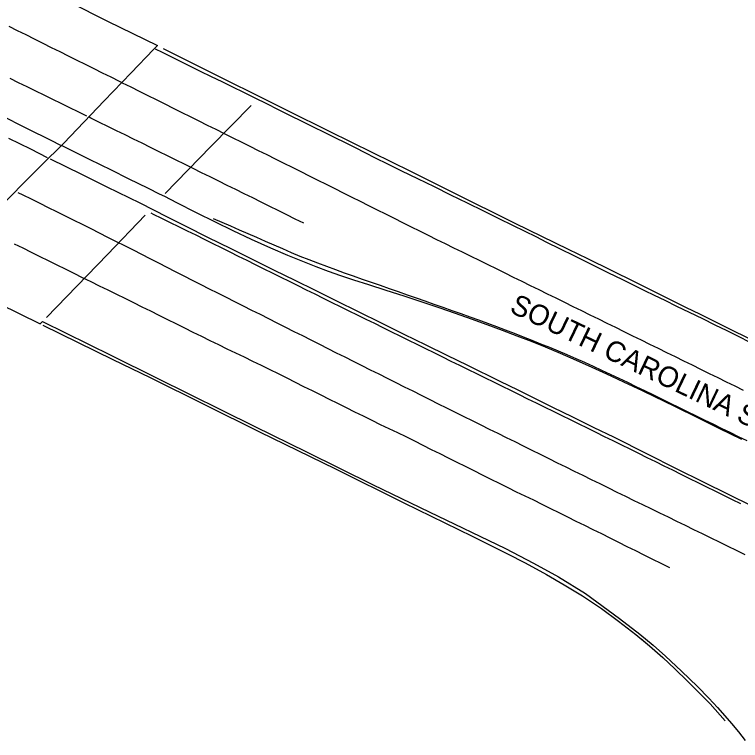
# Model space of a CAD drawing. Extents: x 1961683 to 1977751, y 798292 to 805767.
# Drawn here: x 1963330.2 to 1963521.4, y 799610 to 799801.1 of the extents above; entities that cross this region are included whole.
import ezdxf

# ---------------------------------------------------------------- set-up
doc = ezdxf.new("R2010")
doc.units = 0
for name, color, linetype in [('RD_EX_Bridge', 7, 'Continuous'), ('RD_EX_Conc', 7, 'Continuous'), ('RD_EX_Road', 7, 'Continuous'), ('RD_EX_Road_Paint', 7, 'Continuous'), ('RD_TX_RoadID', 7, 'Continuous')]:
    doc.layers.add(name, color=color, linetype=linetype)

msp = doc.modelspace()

# ---------------------------------------------------------------- linework, layer by layer
at = {"layer": 'RD_EX_Bridge'}
msp.add_lwpolyline([(1963325.6, 799813.75), (1963336.46, 799808.32), (1963344.73, 799804.28), (1963354.67, 799799.34), (1963367.78, 799792.9), (1963366.76, 799791.82), (1963360.89, 799785.69), (1963353.75, 799778.38), (1963343.15, 799767.2), (1963337.18, 799761.34), (1963332.27, 799756.44), (1963323.69, 799747.66)], dxfattribs=at)
at = {"layer": 'RD_EX_Conc'}
for points in [[(1963369.84, 799753.92), (1963381.85, 799766.33), (1963392.52, 799777.14)], [(1963326.11, 799774.71), (1963333.52, 799771.06), (1963339.69, 799768.01), (1963342.3, 799766.71)], [(1963338.88, 799763.39), (1963334.46, 799765.62), (1963328.66, 799768.46)], [(1963521.74, 799689.21), (1963515.78, 799692.13), (1963509.96, 799694.97), (1963504.58, 799697.61), (1963500.99, 799699.37), (1963498.94, 799700.37), (1963495.54, 799702), (1963490.63, 799704.34), (1963486.13, 799706.44), (1963482.26, 799708.2), (1963478.21, 799710), (1963473.95, 799711.86), (1963469.98, 799713.53), (1963466.33, 799715), (1963462.58, 799716.45), (1963458.67, 799717.91), (1963454.63, 799719.39), (1963450.48, 799720.89), (1963446.29, 799722.38), (1963442.04, 799723.85), (1963437.53, 799725.36), (1963432.76, 799726.9), (1963428.05, 799728.42), (1963423.51, 799729.9), (1963419.52, 799731.19), (1963416.09, 799732.32), (1963412.84, 799733.47), (1963409.64, 799734.68), (1963406.12, 799736.05), (1963402.18, 799737.61), (1963397.63, 799739.57), (1963392.56, 799741.88), (1963387.71, 799744.17), (1963383.1, 799746.41), (1963378.1, 799748.9), (1963372.95, 799751.52), (1963369.77, 799753.13), (1963368.36, 799753.83), (1963365.49, 799755.24), (1963360.17, 799757.85), (1963355.71, 799760.06), (1963349.89, 799762.95), (1963342.72, 799766.51)], [(1963339.51, 799763.06), (1963347.79, 799759.03), (1963354.49, 799755.75), (1963363.15, 799751.47), (1963370.36, 799747.84), (1963375.26, 799745.38), (1963381.03, 799742.5), (1963387.1, 799739.46), (1963392.95, 799736.56), (1963398.57, 799733.77), (1963403.96, 799731.12), (1963409.33, 799728.48), (1963414.92, 799725.73), (1963420.7, 799722.88), (1963426.69, 799719.93), (1963432.68, 799716.98), (1963438.47, 799714.13), (1963444.05, 799711.4), (1963449.42, 799708.77), (1963458.01, 799704.57), (1963462.69, 799702.27), (1963467.66, 799699.82), (1963471.83, 799697.77), (1963477.12, 799695.18), (1963482.74, 799692.42), (1963487.89, 799689.88), (1963496.77, 799685.45), (1963504.42, 799681.62), (1963511.5, 799678.09), (1963518.1, 799674.84), (1963524.32, 799671.8)], [(1963338.6, 799721.35), (1963354.63, 799737.94), (1963364.59, 799748.27)]]:
    msp.add_lwpolyline(points, dxfattribs=at)
at = {"layer": 'RD_EX_Road'}
for points in [[(1963523.93, 799714.75), (1963520.8, 799716.31), (1963517.83, 799717.79), (1963514.69, 799719.33), (1963511.4, 799720.94), (1963507.95, 799722.62), (1963504.57, 799724.26), (1963501.48, 799725.76), (1963498.69, 799727.12), (1963496.19, 799728.34), (1963493.55, 799729.63), (1963490.33, 799731.22), (1963486.52, 799733.1), (1963482.13, 799735.27), (1963477.7, 799737.47), (1963473.79, 799739.41), (1963470.39, 799741.09), (1963467.51, 799742.52), (1963464.68, 799743.92), (1963461.44, 799745.52), (1963457.79, 799747.32), (1963453.72, 799749.32), (1963449.43, 799751.43), (1963445.1, 799753.55), (1963440.75, 799755.68), (1963436.36, 799757.82), (1963432.19, 799759.86), (1963428.49, 799761.68), (1963425.26, 799763.28), (1963422.5, 799764.67), (1963419.93, 799765.96), (1963417.29, 799767.28), (1963414.58, 799768.63), (1963411.78, 799770.01), (1963408.9, 799771.42), (1963405.93, 799772.89), (1963402.87, 799774.4), (1963399.72, 799775.96), (1963396.58, 799777.53), (1963393.52, 799779.04), (1963390.55, 799780.51), (1963387.67, 799781.92), (1963384.84, 799783.32), (1963382.01, 799784.7), (1963379.18, 799786.09), (1963376.35, 799787.47), (1963373.66, 799788.79), (1963371.24, 799789.98), (1963369.11, 799791.05), (1963367.25, 799791.98)], [(1963525.71, 799714.75), (1963519.58, 799717.76), (1963514.65, 799720.19), (1963510.79, 799722.09), (1963506.96, 799724), (1963502.38, 799726.27), (1963493.6, 799730.61), (1963487.41, 799733.66), (1963481.17, 799736.73), (1963476.03, 799739.25), (1963469.04, 799742.66), (1963462.05, 799746.08), (1963456.92, 799748.62), (1963450.7, 799751.71), (1963443.28, 799755.39), (1963434.54, 799759.72), (1963424.49, 799764.69), (1963413.13, 799770.31), (1963402.17, 799775.73), (1963393.33, 799780.11), (1963386.6, 799783.45), (1963378.52, 799787.48), (1963372.23, 799790.64), (1963369.4, 799792.07)], [(1963309.51, 799733.08), (1963336.93, 799719.62), (1963337.57, 799720.28), (1963355.71, 799711.33), (1963367.55, 799705.42), (1963393.49, 799692.68), (1963407.1, 799685.97), (1963424.6, 799677.31), (1963439.33, 799670.19), (1963459.48, 799660.5), (1963466.8, 799656.67), (1963473.42, 799653.05), (1963480.5, 799648.67), (1963489.52, 799642.15), (1963494.82, 799638.02), (1963498.4, 799635.09), (1963501.62, 799632.21), (1963505.86, 799628.23), (1963510.03, 799624.19), (1963513.02, 799621.12), (1963515.27, 799618.69), (1963517.2, 799616.52), (1963518.99, 799614.44), (1963520.79, 799612.25), (1963522.58, 799610.01)], [(1963337.59, 799719.33), (1963356.09, 799710.24), (1963365.88, 799705.5), (1963394.69, 799691.26), (1963414.67, 799681.49), (1963432.71, 799672.57), (1963450.67, 799663.8), (1963460, 799659.15), (1963464.63, 799656.8), (1963470.31, 799653.69), (1963474.93, 799651.01), (1963479.72, 799648.11), (1963484.75, 799644.7), (1963489.27, 799641.37), (1963493.79, 799637.92), (1963497.42, 799634.92), (1963500.88, 799631.85), (1963504.06, 799628.87), (1963507.4, 799625.65), (1963509.83, 799623.2), (1963513.35, 799619.63), (1963517.33, 799615.21)], [(1963495.12, 799636.82), (1963497.42, 799634.92), (1963500.88, 799631.85), (1963504.06, 799628.87), (1963507.4, 799625.65), (1963509.83, 799623.2), (1963513.35, 799619.63), (1963517.33, 799615.21)]]:
    msp.add_lwpolyline(points, dxfattribs=at)
at = {"layer": 'RD_EX_Road_Paint'}
for points in [[(1963328.63, 799798), (1963330.87, 799796.88), (1963333.11, 799795.77), (1963335.34, 799794.65), (1963337.58, 799793.54), (1963339.82, 799792.43), (1963342.06, 799791.31), (1963344.3, 799790.2), (1963346.53, 799789.08), (1963348.77, 799787.97), (1963351.01, 799786.86), (1963353.25, 799785.74), (1963355.49, 799784.63), (1963357.72, 799783.52), (1963358.28, 799783.24)], [(1963349.2, 799774.33), (1963346.96, 799775.43), (1963344.71, 799776.53), (1963342.47, 799777.63), (1963340.23, 799778.73), (1963337.98, 799779.83), (1963335.74, 799780.93), (1963333.49, 799782.03), (1963331.25, 799783.13), (1963329, 799784.24)], [(1963358.54, 799783.11), (1963360.77, 799782), (1963363.01, 799780.88), (1963365.25, 799779.77), (1963367.49, 799778.66), (1963369.73, 799777.54), (1963371.97, 799776.43), (1963374.2, 799775.32), (1963376.44, 799774.21), (1963378.68, 799773.09), (1963380.92, 799771.98), (1963383.16, 799770.87), (1963385.4, 799769.76), (1963387.63, 799768.64), (1963389.87, 799767.53), (1963392.11, 799766.42), (1963394.35, 799765.31), (1963396.59, 799764.19), (1963398.83, 799763.08), (1963401.07, 799761.97), (1963403.3, 799760.85), (1963405.54, 799759.74), (1963407.78, 799758.62), (1963410.01, 799757.51), (1963412.25, 799756.39), (1963414.48, 799755.27), (1963416.72, 799754.16), (1963418.96, 799753.04), (1963421.19, 799751.92), (1963423.43, 799750.81), (1963425.67, 799749.69), (1963427.9, 799748.58), (1963430.14, 799747.46), (1963432.37, 799746.34), (1963434.61, 799745.23), (1963436.85, 799744.11), (1963439.08, 799743), (1963441.33, 799741.89), (1963443.57, 799740.79), (1963445.81, 799739.69), (1963448.06, 799738.59), (1963450.3, 799737.48), (1963452.54, 799736.38), (1963454.78, 799735.28), (1963457.03, 799734.18), (1963459.27, 799733.07), (1963461.51, 799731.97), (1963463.76, 799730.87), (1963466, 799729.76), (1963468.24, 799728.66), (1963470.48, 799727.56), (1963472.73, 799726.46), (1963474.97, 799725.35), (1963477.21, 799724.25), (1963479.46, 799723.15), (1963481.7, 799722.05), (1963483.94, 799720.95), (1963486.19, 799719.85), (1963488.43, 799718.75), (1963490.67, 799717.65), (1963492.92, 799716.54), (1963495.16, 799715.44), (1963497.4, 799714.34), (1963499.65, 799713.24), (1963501.89, 799712.14), (1963504.13, 799711.04), (1963506.38, 799709.94), (1963508.62, 799708.84), (1963510.86, 799707.74), (1963513.11, 799706.63), (1963515.35, 799705.53), (1963517.6, 799704.43), (1963519.84, 799703.33), (1963522.08, 799702.23)], [(1963406.33, 799746.14), (1963404.09, 799747.25), (1963401.85, 799748.36), (1963399.61, 799749.47), (1963397.37, 799750.57), (1963395.13, 799751.68), (1963392.89, 799752.79), (1963390.65, 799753.9), (1963388.41, 799755.01), (1963386.17, 799756.11), (1963383.93, 799757.22), (1963381.69, 799758.33), (1963379.45, 799759.44), (1963377.21, 799760.54), (1963374.97, 799761.65), (1963372.73, 799762.76), (1963370.49, 799763.87), (1963368.25, 799764.97), (1963366, 799766.08), (1963363.76, 799767.19), (1963361.52, 799768.29), (1963359.27, 799769.39), (1963357.03, 799770.49), (1963354.78, 799771.59), (1963352.54, 799772.69), (1963350.3, 799773.79), (1963349.83, 799774.02)], [(1963522.58, 799658.88), (1963520.34, 799659.98), (1963518.09, 799661.07), (1963515.85, 799662.17), (1963513.6, 799663.26), (1963511.35, 799664.36), (1963509.11, 799665.46), (1963506.86, 799666.55), (1963504.61, 799667.65), (1963502.37, 799668.74), (1963500.12, 799669.84), (1963497.87, 799670.93), (1963495.63, 799672.03), (1963493.38, 799673.12), (1963491.13, 799674.22), (1963488.89, 799675.31), (1963486.64, 799676.41), (1963484.39, 799677.51), (1963482.15, 799678.61), (1963479.91, 799679.72), (1963477.67, 799680.82), (1963475.43, 799681.93), (1963473.19, 799683.03), (1963470.95, 799684.14), (1963468.7, 799685.25), (1963466.46, 799686.35), (1963464.22, 799687.46), (1963461.98, 799688.57), (1963459.74, 799689.67), (1963457.5, 799690.78), (1963455.26, 799691.89), (1963453.02, 799692.99), (1963450.78, 799694.1), (1963448.54, 799695.21), (1963446.3, 799696.32), (1963444.06, 799697.44), (1963441.83, 799698.56), (1963439.59, 799699.68), (1963437.36, 799700.79), (1963435.12, 799701.91), (1963432.89, 799703.03), (1963430.65, 799704.15), (1963428.42, 799705.26), (1963426.18, 799706.38), (1963423.94, 799707.5), (1963421.71, 799708.62), (1963419.47, 799709.74), (1963417.24, 799710.85), (1963415, 799711.97), (1963412.77, 799713.09), (1963410.53, 799714.21), (1963408.3, 799715.34), (1963406.07, 799716.46), (1963403.84, 799717.58), (1963401.6, 799718.71), (1963399.37, 799719.83), (1963397.14, 799720.96), (1963394.91, 799722.08), (1963392.68, 799723.2), (1963390.44, 799724.33), (1963388.21, 799725.45), (1963385.98, 799726.58), (1963383.75, 799727.7), (1963381.51, 799728.82), (1963379.28, 799729.95), (1963377.05, 799731.07), (1963374.82, 799732.2), (1963372.59, 799733.34), (1963370.36, 799734.47), (1963368.14, 799735.61), (1963365.91, 799736.74), (1963363.68, 799737.88), (1963361.46, 799739.01), (1963359.23, 799740.15), (1963357, 799741.28), (1963354.78, 799742.42), (1963352.55, 799743.55), (1963350.31, 799744.66), (1963348.07, 799745.77), (1963345.83, 799746.88), (1963343.59, 799747.99), (1963341.35, 799749.1), (1963339.11, 799750.22), (1963336.88, 799751.33), (1963334.64, 799752.44), (1963332.4, 799753.56), (1963331.14, 799754.18)], [(1963521.45, 799672.28), (1963519.21, 799673.38), (1963516.97, 799674.49), (1963514.73, 799675.59), (1963512.49, 799676.7), (1963510.24, 799677.8), (1963508, 799678.9), (1963505.76, 799680.01), (1963503.52, 799681.11), (1963501.28, 799682.22), (1963499.03, 799683.32), (1963496.79, 799684.43), (1963494.55, 799685.53), (1963492.31, 799686.64), (1963490.07, 799687.74), (1963487.82, 799688.85), (1963485.58, 799689.95), (1963483.34, 799691.06), (1963481.1, 799692.16), (1963478.86, 799693.27), (1963476.61, 799694.37), (1963474.37, 799695.47), (1963472.13, 799696.57), (1963469.88, 799697.67), (1963467.64, 799698.77), (1963465.39, 799699.87), (1963463.15, 799700.98), (1963460.91, 799702.08), (1963458.66, 799703.18), (1963456.42, 799704.28), (1963454.18, 799705.38), (1963451.93, 799706.48), (1963449.69, 799707.58), (1963447.45, 799708.69), (1963445.2, 799709.79), (1963442.96, 799710.89), (1963440.72, 799711.99), (1963438.47, 799713.1), (1963436.23, 799714.2), (1963433.99, 799715.3), (1963431.75, 799716.4), (1963429.5, 799717.51), (1963427.26, 799718.61), (1963425.02, 799719.71), (1963422.77, 799720.82), (1963420.53, 799721.92), (1963418.29, 799723.02), (1963416.05, 799724.12), (1963413.8, 799725.23), (1963411.56, 799726.33), (1963409.32, 799727.43), (1963407.08, 799728.54), (1963404.84, 799729.65), (1963402.6, 799730.76), (1963400.36, 799731.87), (1963398.12, 799732.98), (1963395.88, 799734.09), (1963393.64, 799735.2), (1963391.4, 799736.31), (1963389.16, 799737.42), (1963386.92, 799738.53), (1963384.68, 799739.64), (1963382.45, 799740.75), (1963380.21, 799741.86), (1963377.97, 799742.97), (1963375.73, 799744.08), (1963373.48, 799745.18), (1963371.24, 799746.27), (1963368.99, 799747.37), (1963366.74, 799748.46), (1963366.12, 799748.76)], [(1963382.46, 799747.4), (1963384.75, 799746.4), (1963387.03, 799745.41), (1963389.32, 799744.42), (1963391.61, 799743.43), (1963393.89, 799742.44), (1963396.18, 799741.45), (1963398.47, 799740.45), (1963400.75, 799739.46), (1963403.04, 799738.47), (1963405.33, 799737.48), (1963407.64, 799736.55), (1963409.98, 799735.68), (1963412.33, 799734.81), (1963414.67, 799733.95), (1963417.02, 799733.09), (1963419.37, 799732.26), (1963421.73, 799731.43), (1963424.1, 799730.62), (1963426.47, 799729.82), (1963428.82, 799728.99), (1963431.18, 799728.15), (1963433.53, 799727.32), (1963435.9, 799726.51), (1963438.26, 799725.68), (1963440.61, 799724.85), (1963442.97, 799724.01), (1963445.32, 799723.18), (1963447.68, 799722.36), (1963450.04, 799721.53), (1963452.39, 799720.68), (1963454.74, 799719.81), (1963457.08, 799718.94), (1963459.42, 799718.06), (1963461.75, 799717.17), (1963464.08, 799716.27), (1963466.41, 799715.35), (1963468.73, 799714.43), (1963471.05, 799713.49), (1963473.36, 799712.53), (1963475.65, 799711.55), (1963477.95, 799710.56), (1963480.24, 799709.56), (1963482.52, 799708.54), (1963484.79, 799707.5), (1963487.06, 799706.44), (1963489.32, 799705.37), (1963491.57, 799704.3), (1963493.82, 799703.21), (1963496.07, 799702.11), (1963498.31, 799701.02), (1963500.56, 799699.92), (1963502.8, 799698.82), (1963505.05, 799697.72), (1963507.29, 799696.62), (1963509.54, 799695.52), (1963511.78, 799694.42), (1963514.03, 799693.32), (1963516.27, 799692.22), (1963518.52, 799691.13), (1963520.76, 799690.03), (1963523.01, 799688.93)], [(1963502.72, 799655.44), (1963500.49, 799656.56), (1963498.25, 799657.68), (1963496.01, 799658.79), (1963493.77, 799659.9), (1963491.53, 799661.01), (1963489.3, 799662.12), (1963487.06, 799663.23), (1963484.82, 799664.35), (1963482.58, 799665.46), (1963480.34, 799666.57), (1963478.1, 799667.68), (1963475.86, 799668.79), (1963473.62, 799669.9), (1963471.39, 799671.01), (1963469.15, 799672.13), (1963466.91, 799673.23), (1963464.65, 799674.32), (1963462.4, 799675.4), (1963460.16, 799676.5), (1963457.92, 799677.61), (1963455.68, 799678.72), (1963453.44, 799679.84), (1963451.21, 799680.95), (1963448.97, 799682.07), (1963446.73, 799683.18), (1963444.5, 799684.3), (1963442.26, 799685.41), (1963440.02, 799686.53), (1963437.79, 799687.64), (1963435.55, 799688.76), (1963433.31, 799689.88), (1963431.07, 799690.98), (1963428.81, 799692.05), (1963426.56, 799693.12), (1963424.31, 799694.22), (1963422.07, 799695.32), (1963419.83, 799696.44), (1963417.59, 799697.55), (1963415.35, 799698.66), (1963413.12, 799699.78), (1963410.88, 799700.89), (1963408.64, 799702), (1963406.4, 799703.12), (1963404.17, 799704.23), (1963401.93, 799705.34), (1963399.69, 799706.46), (1963397.45, 799707.57), (1963395.21, 799708.68), (1963392.96, 799709.77), (1963390.71, 799710.85), (1963388.45, 799711.91), (1963386.19, 799712.98), (1963383.95, 799714.09), (1963381.71, 799715.2), (1963379.47, 799716.31), (1963377.23, 799717.42), (1963374.99, 799718.53), (1963372.75, 799719.64), (1963370.51, 799720.75), (1963368.27, 799721.86), (1963366.04, 799722.98), (1963363.8, 799724.09), (1963361.56, 799725.2), (1963359.32, 799726.31), (1963357.08, 799727.41), (1963354.83, 799728.51), (1963352.58, 799729.59), (1963350.33, 799730.69), (1963348.09, 799731.8), (1963345.85, 799732.91), (1963343.61, 799734.01), (1963341.37, 799735.12), (1963339.13, 799736.22), (1963336.88, 799737.33), (1963334.64, 799738.44), (1963332.4, 799739.54), (1963330.16, 799740.65)]]:
    msp.add_lwpolyline(points, dxfattribs=at)

# ---------------------------------------------------------------- texts
at = {"layer": 'RD_TX_RoadID'}
msp.add_text('SOUTH CAROLINA S-32-107 bush river', height=5.4, rotation=334.4085, dxfattribs=at).set_placement((1963460.28, 799722.86))

doc.saveas('drawing.dxf')
